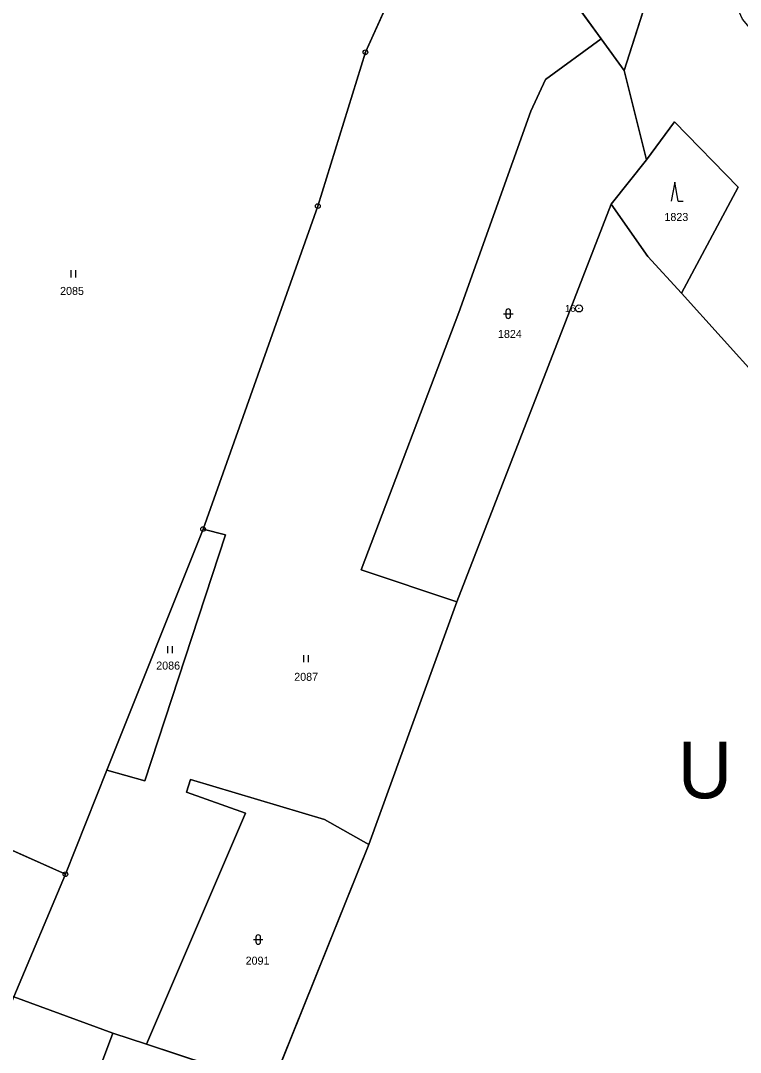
# Model space of a CAD drawing. Extents: x -689422 to -685210, y -987725 to -982160.
# Drawn here: x -688116.8 to -687963.9, y -985617.6 to -985398.5 of the extents above; entities that cross this region are included whole.
import ezdxf

# ---------------------------------------------------------------- set-up
doc = ezdxf.new("R2010")
doc.units = 0
for name, color, linetype in [('KN_Hranice_parcel', 7, 'Continuous'), ('KN_Parcelni cisla', 7, 'Continuous'), ('KN_Polygon parcely', 7, 'Continuous'), ('KN_Popisy_pomistni nazvy', 7, 'Continuous'), ('KN_POZEMKY_LESNI POZEMEK', 7, 'Continuous'), ('KN_POZEMKY_ORNA PUDA', 7, 'Continuous'), ('KN_POZEMKY_OSTATNI PLOCHA', 7, 'Continuous'), ('KN_POZEMKY_TTP', 7, 'Continuous'), ('KN_VYUZITI_27_ostatni plocha_neplodna puda', 7, 'Continuous'), ('KN_Značky bodu BP', 7, 'Continuous'), ('KN_Značky kultur', 7, 'Continuous')]:
    doc.layers.add(name, color=color, linetype=linetype)

msp = doc.modelspace()

# ---------------------------------------------------------------- linework, layer by layer
at = {"layer": 'KN_Hranice_parcel'}
for p, q in [((-687993.48, -985402.39), (-688000.74, -985392.41)), ((-687988.59, -985409.1), (-687993.48, -985402.39)), ((-687988.59, -985409.1), (-687983.9, -985428.09)), ((-687983.9, -985428.09), (-687991.36, -985437.52)), ((-688024.15, -985521.96), (-687991.36, -985437.52)), ((-687976.45, -985456.42), (-687959.62, -985475.12)), ((-688078.03, -985506.51), (-688098.45, -985557.71)), ((-688024.15, -985521.96), (-688042.86, -985573.48)), ((-688098.45, -985557.71), (-688107.26, -985579.81)), ((-688042.86, -985573.48), (-688063.44, -985624.68)), ((-688107.26, -985579.81), (-688118.23, -985605.82)), ((-688118.23, -985605.82), (-688097.2, -985613.53)), ((-688115.94, -985663.71), (-688097.2, -985613.53)), ((-688097.2, -985613.53), (-688090.01, -985615.86)), ((-688090.01, -985615.86), (-688063.44, -985624.68))]:
    msp.add_line(p, q, dxfattribs=at)
for points in [[(-687980.13, -985361.3), (-687982.26, -985389.13), (-687988.59, -985409.1)], [(-688023.59, -985374.19), (-688034.95, -985386.23), (-688043.57, -985405.26), (-688053.66, -985437.92), (-688078.03, -985506.51)], [(-687993.48, -985402.39), (-688005.35, -985411.06), (-688008.43, -985417.76), (-688023.71, -985460.48), (-688044.49, -985515.16), (-688024.15, -985521.96)], [(-687983.9, -985428.09), (-687977.9, -985420.03), (-687964.42, -985433.86), (-687976.45, -985456.42)], [(-687991.36, -985437.52), (-687983.62, -985448.63), (-687976.45, -985456.42)], [(-688098.45, -985557.71), (-688090.36, -985559.95), (-688073.26, -985507.74), (-688078.03, -985506.51)], [(-688107.26, -985579.81), (-688143.55, -985563.59), (-688164.68, -985551.96)], [(-688090.01, -985615.86), (-688069.02, -985566.8), (-688081.55, -985562.39), (-688080.68, -985559.65), (-688052.26, -985568.21), (-688042.86, -985573.48)]]:
    msp.add_lwpolyline(points, dxfattribs=at)
at = {"layer": 'KN_Polygon parcely'}
for points in [[(-688117.94, -985339.46), (-688117.58, -985358), (-688172.09, -985517.46), (-688164.48, -985537.87), (-688164.68, -985551.96), (-688143.55, -985563.59), (-688107.26, -985579.81), (-688098.45, -985557.71), (-688078.03, -985506.51), (-688053.66, -985437.92), (-688043.57, -985405.26), (-688034.95, -985386.23), (-688023.59, -985374.19), (-688019.27, -985369.61), (-688052.69, -985361.11), (-688076.49, -985356.58), (-688080.38, -985355.43), (-688097.3, -985350.44), (-688112.74, -985345.88), (-688116.59, -985295.07)], [(-688023.59, -985374.19), (-688000.74, -985392.41), (-687993.48, -985402.39), (-687988.59, -985409.1), (-687982.26, -985389.13), (-687980.13, -985361.3), (-687979.9, -985358.31), (-688019.27, -985369.61)], [(-687983.9, -985428.09), (-687977.9, -985420.03), (-687964.42, -985433.86), (-687976.45, -985456.42), (-687959.62, -985475.12), (-687943.65, -985460.48), (-687931.93, -985448.63), (-687944.1, -985427.38), (-687941.16, -985425.07), (-687963.48, -985398.25), (-687980.13, -985361.3), (-687982.26, -985389.13), (-687988.59, -985409.1)], [(-688034.95, -985386.23), (-688043.57, -985405.26), (-688053.66, -985437.92), (-688078.03, -985506.51), (-688073.26, -985507.74), (-688090.36, -985559.95), (-688098.45, -985557.71), (-688107.26, -985579.81), (-688118.23, -985605.82), (-688097.2, -985613.53), (-688090.01, -985615.86), (-688069.02, -985566.8), (-688081.55, -985562.39), (-688080.68, -985559.65), (-688052.26, -985568.21), (-688042.86, -985573.48), (-688024.15, -985521.96), (-688044.49, -985515.16), (-688023.71, -985460.48), (-688008.43, -985417.76), (-688005.35, -985411.06), (-687993.48, -985402.39), (-688000.74, -985392.41), (-688023.59, -985374.19)], [(-687988.59, -985409.1), (-687993.48, -985402.39), (-688005.35, -985411.06), (-688008.43, -985417.76), (-688023.71, -985460.48), (-688044.49, -985515.16), (-688024.15, -985521.96), (-687991.36, -985437.52), (-687983.9, -985428.09)], [(-687976.45, -985456.42), (-687964.42, -985433.86), (-687977.9, -985420.03), (-687983.9, -985428.09), (-687991.36, -985437.52), (-687983.62, -985448.63)], [(-688024.15, -985521.96), (-688042.86, -985573.48), (-688063.44, -985624.68), (-688083.89, -985677.77), (-688087.28, -985687.49), (-688088.7, -985692.07), (-688090.63, -985698.27), (-688098.59, -985721.04), (-688060.69, -985733.68), (-688043.61, -985739.06), (-687929.48, -985774.84), (-687884.77, -985606.4), (-687883.66, -985582.05), (-687896.67, -985563.46), (-687907.32, -985547.67), (-687919.71, -985527.65), (-687927.72, -985516.43), (-687939.14, -985503.4), (-687949.38, -985491.72), (-687959.62, -985475.12), (-687976.45, -985456.42), (-687983.62, -985448.63), (-687991.36, -985437.52)], [(-688073.26, -985507.74), (-688078.03, -985506.51), (-688098.45, -985557.71), (-688090.36, -985559.95)], [(-688164.75, -985589.88), (-688118.23, -985605.82), (-688107.26, -985579.81), (-688143.55, -985563.59), (-688164.68, -985551.96), (-688168.74, -985549.85), (-688179.63, -985582.83), (-688181.02, -985582.14), (-688182.2, -985586.51), (-688176.41, -985588.19), (-688175.94, -985586.71), (-688166.51, -985556.96), (-688155.71, -985564.08)], [(-688090.01, -985615.86), (-688063.44, -985624.68), (-688042.86, -985573.48), (-688052.26, -985568.21), (-688080.68, -985559.65), (-688081.55, -985562.39), (-688069.02, -985566.8)], [(-688135.05, -985644.65), (-688139.49, -985653.2), (-688115.94, -985663.71), (-688097.2, -985613.53), (-688118.23, -985605.82)], [(-688115.94, -985663.71), (-688083.89, -985677.77), (-688063.44, -985624.68), (-688090.01, -985615.86), (-688097.2, -985613.53)]]:
    msp.add_lwpolyline(points, close=True, dxfattribs=at)
at = {"layer": 'KN_POZEMKY_LESNI POZEMEK'}
for p, q in [((-687982.26, -985389.13), (-687988.59, -985409.1)), ((-687993.48, -985402.39), (-688000.74, -985392.41)), ((-687988.59, -985409.1), (-687993.48, -985402.39)), ((-687983.9, -985428.09), (-687977.9, -985420.03)), ((-687977.9, -985420.03), (-687964.42, -985433.86)), ((-687991.36, -985437.52), (-687983.9, -985428.09)), ((-687964.42, -985433.86), (-687976.45, -985456.42)), ((-687983.62, -985448.63), (-687991.36, -985437.52)), ((-687976.45, -985456.42), (-687983.62, -985448.63))]:
    msp.add_line(p, q, dxfattribs=at)
at = {"layer": 'KN_POZEMKY_ORNA PUDA'}
for p, q in [((-688024.15, -985521.96), (-687991.36, -985437.52)), ((-687991.36, -985437.52), (-687983.62, -985448.63)), ((-687983.62, -985448.63), (-687976.45, -985456.42)), ((-687976.45, -985456.42), (-687959.62, -985475.12)), ((-688042.86, -985573.48), (-688024.15, -985521.96)), ((-688063.44, -985624.68), (-688042.86, -985573.48))]:
    msp.add_line(p, q, dxfattribs=at)
at = {"layer": 'KN_POZEMKY_OSTATNI PLOCHA'}
for p, q in [((-688005.35, -985411.06), (-687993.48, -985402.39)), ((-687993.48, -985402.39), (-687988.59, -985409.1)), ((-687988.59, -985409.1), (-687983.9, -985428.09)), ((-688008.43, -985417.76), (-688005.35, -985411.06)), ((-688023.71, -985460.48), (-688008.43, -985417.76)), ((-687983.9, -985428.09), (-687991.36, -985437.52)), ((-687991.36, -985437.52), (-688024.15, -985521.96)), ((-688044.49, -985515.16), (-688023.71, -985460.48)), ((-688024.15, -985521.96), (-688044.49, -985515.16)), ((-688081.55, -985562.39), (-688080.68, -985559.65)), ((-688080.68, -985559.65), (-688052.26, -985568.21)), ((-688069.02, -985566.8), (-688081.55, -985562.39)), ((-688090.01, -985615.86), (-688069.02, -985566.8)), ((-688052.26, -985568.21), (-688042.86, -985573.48)), ((-688042.86, -985573.48), (-688063.44, -985624.68)), ((-688115.94, -985663.71), (-688097.2, -985613.53)), ((-688097.2, -985613.53), (-688090.01, -985615.86)), ((-688063.44, -985624.68), (-688090.01, -985615.86)), ((-688090.01, -985615.86), (-688063.44, -985624.68))]:
    msp.add_line(p, q, dxfattribs=at)
at = {"layer": 'KN_POZEMKY_TTP'}
for p, q in [((-688034.95, -985386.23), (-688043.57, -985405.26)), ((-688043.57, -985405.26), (-688034.95, -985386.23)), ((-687988.59, -985409.1), (-687982.26, -985389.13)), ((-688000.74, -985392.41), (-687993.48, -985402.39)), ((-687993.48, -985402.39), (-688005.35, -985411.06)), ((-688043.57, -985405.26), (-688053.66, -985437.92)), ((-688053.66, -985437.92), (-688043.57, -985405.26)), ((-687983.9, -985428.09), (-687988.59, -985409.1)), ((-688005.35, -985411.06), (-688008.43, -985417.76)), ((-688008.43, -985417.76), (-688023.71, -985460.48)), ((-687977.9, -985420.03), (-687983.9, -985428.09)), ((-687964.42, -985433.86), (-687977.9, -985420.03)), ((-687976.45, -985456.42), (-687964.42, -985433.86)), ((-688053.66, -985437.92), (-688078.03, -985506.51)), ((-688078.03, -985506.51), (-688053.66, -985437.92)), ((-687959.62, -985475.12), (-687976.45, -985456.42)), ((-688023.71, -985460.48), (-688044.49, -985515.16)), ((-688098.45, -985557.71), (-688078.03, -985506.51)), ((-688078.03, -985506.51), (-688098.45, -985557.71)), ((-688078.03, -985506.51), (-688073.26, -985507.74)), ((-688073.26, -985507.74), (-688078.03, -985506.51)), ((-688073.26, -985507.74), (-688090.36, -985559.95)), ((-688090.36, -985559.95), (-688073.26, -985507.74)), ((-688044.49, -985515.16), (-688024.15, -985521.96)), ((-688024.15, -985521.96), (-688042.86, -985573.48)), ((-688098.45, -985557.71), (-688107.26, -985579.81)), ((-688107.26, -985579.81), (-688098.45, -985557.71)), ((-688090.36, -985559.95), (-688098.45, -985557.71)), ((-688098.45, -985557.71), (-688090.36, -985559.95)), ((-688080.68, -985559.65), (-688081.55, -985562.39)), ((-688052.26, -985568.21), (-688080.68, -985559.65)), ((-688107.26, -985579.81), (-688143.55, -985563.59)), ((-688143.55, -985563.59), (-688107.26, -985579.81)), ((-688081.55, -985562.39), (-688069.02, -985566.8)), ((-688069.02, -985566.8), (-688090.01, -985615.86)), ((-688042.86, -985573.48), (-688052.26, -985568.21)), ((-688118.23, -985605.82), (-688107.26, -985579.81)), ((-688107.26, -985579.81), (-688118.23, -985605.82)), ((-688118.23, -985605.82), (-688097.2, -985613.53)), ((-688097.2, -985613.53), (-688118.23, -985605.82)), ((-688097.2, -985613.53), (-688115.94, -985663.71)), ((-688090.01, -985615.86), (-688097.2, -985613.53))]:
    msp.add_line(p, q, dxfattribs=at)
at = {"layer": 'KN_VYUZITI_27_ostatni plocha_neplodna puda'}
for p, q in [((-688005.35, -985411.06), (-687993.48, -985402.39)), ((-687993.48, -985402.39), (-687988.59, -985409.1)), ((-687988.59, -985409.1), (-687983.9, -985428.09)), ((-688008.43, -985417.76), (-688005.35, -985411.06)), ((-688023.71, -985460.48), (-688008.43, -985417.76)), ((-687983.9, -985428.09), (-687991.36, -985437.52)), ((-687991.36, -985437.52), (-688024.15, -985521.96)), ((-688044.49, -985515.16), (-688023.71, -985460.48)), ((-688024.15, -985521.96), (-688044.49, -985515.16)), ((-688081.55, -985562.39), (-688080.68, -985559.65)), ((-688080.68, -985559.65), (-688052.26, -985568.21)), ((-688069.02, -985566.8), (-688081.55, -985562.39)), ((-688090.01, -985615.86), (-688069.02, -985566.8)), ((-688052.26, -985568.21), (-688042.86, -985573.48)), ((-688042.86, -985573.48), (-688063.44, -985624.68)), ((-688115.94, -985663.71), (-688097.2, -985613.53)), ((-688097.2, -985613.53), (-688090.01, -985615.86)), ((-688063.44, -985624.68), (-688090.01, -985615.86)), ((-688090.01, -985615.86), (-688063.44, -985624.68))]:
    msp.add_line(p, q, dxfattribs=at)
at = {"layer": 'KN_Značky bodu BP'}
for centre, radius in [((-688043.57, -985405.26), 0.5), ((-688043.57, -985405.26), 0.0303), ((-688053.66, -985437.92), 0.5), ((-688053.66, -985437.92), 0.0303), ((-687998.21, -985459.65), 0.75), ((-687998.21, -985459.65), 0.03), ((-688078.03, -985506.51), 0.5), ((-688078.03, -985506.51), 0.0303), ((-688107.26, -985579.81), 0.5), ((-688107.26, -985579.81), 0.0303)]:
    msp.add_circle(centre, radius, dxfattribs=at)
at = {"layer": 'KN_Značky kultur'}
for p, q in [((-687977.87, -985432.85), (-687978.62, -985436.85)), ((-687977.12, -985436.85), (-687977.87, -985432.85)), ((-687977.12, -985436.85), (-687976.12, -985436.85)), ((-688106.06, -985453.05), (-688106.06, -985451.55)), ((-688105.06, -985453.05), (-688105.06, -985451.55)), ((-688014.22, -985460.76), (-688012.22, -985460.76)), ((-688013.72, -985460.26), (-688013.72, -985461.26)), ((-688012.72, -985461.26), (-688012.72, -985460.26)), ((-688085.49, -985532.85), (-688085.49, -985531.35)), ((-688084.49, -985532.85), (-688084.49, -985531.35)), ((-688056.63, -985534.76), (-688056.63, -985533.26)), ((-688055.63, -985534.76), (-688055.63, -985533.26)), ((-688067.32, -985593.68), (-688065.32, -985593.68)), ((-688066.82, -985593.18), (-688066.82, -985594.18)), ((-688065.82, -985594.18), (-688065.82, -985593.18))]:
    msp.add_line(p, q, dxfattribs=at)
for centre, start, end in [((-688013.22, -985460.26), 0, 180), ((-688013.22, -985461.26), 180, 359.9879), ((-688066.32, -985593.18), 0, 180), ((-688066.32, -985594.18), 180, 359.9879)]:
    msp.add_arc(centre, 0.5, start, end, dxfattribs=at)

# ---------------------------------------------------------------- texts
at = {"layer": 'KN_Parcelni cisla'}
for s, p in [('1823', (-687980.07, -985441.07)), ('2085', (-688108.38, -985456.78)), ('1824', (-688015.41, -985465.92)), ('2086', (-688087.97, -985536.34)), ('2087', (-688058.67, -985538.73)), ('2091', (-688068.99, -985599.01))]:
    msp.add_text(s, height=1.7, dxfattribs=at).set_placement(p)
at = {"layer": 'KN_Popisy_pomistni nazvy'}
msp.add_text('U šibenice', height=12, dxfattribs=at).set_placement((-687977.25, -985563.68))
at = {"layer": 'KN_Značky bodu BP'}
msp.add_text('16', height=1.5, dxfattribs=at).set_placement((-688001.17, -985460.4))

doc.saveas('drawing.dxf')
